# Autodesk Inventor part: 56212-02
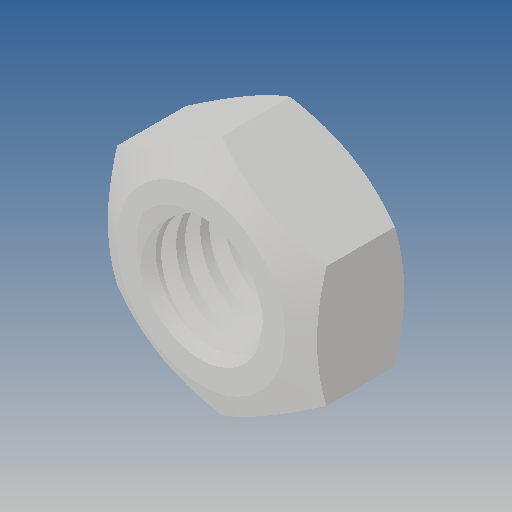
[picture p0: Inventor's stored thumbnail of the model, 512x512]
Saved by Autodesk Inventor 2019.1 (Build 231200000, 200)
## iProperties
Created: 2011-05
Part Number: 56212-02
Material: Ogólny
Document SubType Name: Modeling
Designer: CADENGINEERING4
Density: 1 g/cm^3
Appearance: Domyślna
Author: CADENGINEERING4
Revision Number: ÈÎºÎ
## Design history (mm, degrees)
feature "¾µÏò1"
node "Bryła1"
